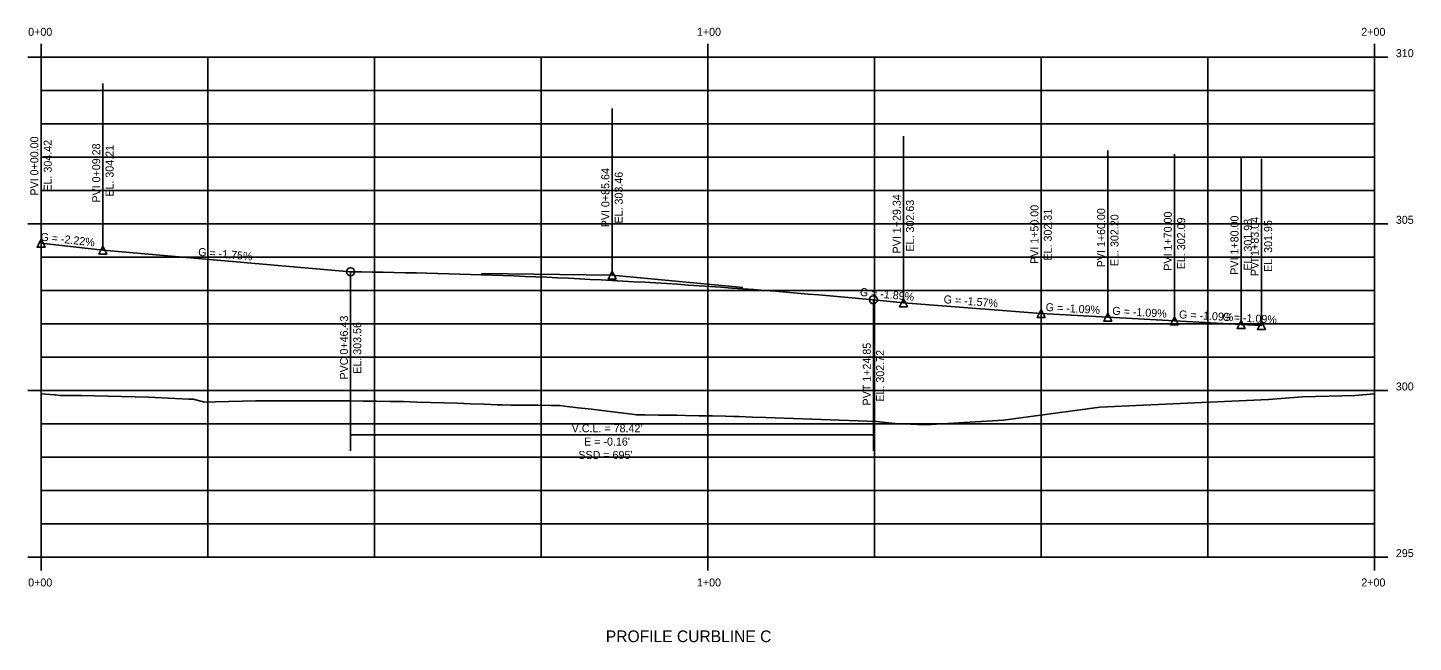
# Model space of a CAD drawing. Extents: x 916627 to 921213, y 329780 to 330157.
# Drawn here: x 920569.3 to 920777.1, y 329813.5 to 329905.7 of the extents above; entities that cross this region are included whole.
import ezdxf

# ---------------------------------------------------------------- set-up
doc = ezdxf.new("R2010")
doc.units = 0
for name, color, linetype in [('D_Roadway_Centerline', 7, 'Continuous'), ('D_Roadway_Centerline_Bearings', 7, 'Continuous'), ('D_Roadway_Centerline_CurveData', 7, 'Continuous'), ('D_Roadway_Centerline_Text', 7, 'Continuous')]:
    doc.layers.add(name, color=color, linetype=linetype)

msp = doc.modelspace()

# ---------------------------------------------------------------- linework, layer by layer
at = {"layer": 'D_Roadway_Centerline'}
for p, q in [((920571.31, 329903.28), (920571.31, 329901.28)), ((920671.31, 329903.28), (920671.31, 329901.28)), ((920771.31, 329903.28), (920771.31, 329901.28)), ((920771.31, 329903.28), (920771.31, 329901.28)), ((920569.31, 329901.28), (920571.31, 329901.28)), ((920569.31, 329901.28), (920571.31, 329901.28)), ((920571.31, 329901.28), (920771.31, 329901.28)), ((920571.31, 329826.28), (920571.31, 329901.28)), ((920671.31, 329826.28), (920671.31, 329901.28)), ((920771.31, 329826.28), (920771.31, 329901.28)), ((920773.31, 329901.28), (920771.31, 329901.28)), ((920773.31, 329901.28), (920771.31, 329901.28)), ((920569.31, 329876.28), (920571.31, 329876.28)), ((920571.31, 329876.28), (920771.31, 329876.28)), ((920773.31, 329876.28), (920771.31, 329876.28)), ((920571.31, 329873.36), (920580.59, 329872.33)), ((920580.59, 329872.33), (920617.74, 329869.08)), ((920696.16, 329864.88), (920700.65, 329864.45)), ((920700.65, 329864.45), (920721.31, 329862.83)), ((920721.31, 329862.83), (920731.31, 329862.29)), ((920731.31, 329862.29), (920741.31, 329861.74)), ((920741.31, 329861.74), (920751.31, 329861.19)), ((920751.31, 329861.19), (920754.35, 329861.03)), ((920569.31, 329851.28), (920571.31, 329851.28)), ((920571.31, 329851.28), (920771.31, 329851.28)), ((920773.31, 329851.28), (920771.31, 329851.28)), ((920569.31, 329826.28), (920571.31, 329826.28)), ((920571.31, 329824.28), (920571.31, 329826.28)), ((920571.31, 329826.28), (920771.31, 329826.28)), ((920671.31, 329824.28), (920671.31, 329826.28)), ((920773.31, 329826.28), (920771.31, 329826.28)), ((920771.31, 329824.28), (920771.31, 329826.28)), ((920771.31, 329824.28), (920771.31, 329826.28))]:
    msp.add_line(p, q, dxfattribs=at)
msp.add_lwpolyline([(920617.74, 329869.08), (920619.38, 329869.06), (920621.01, 329869.03), (920622.64, 329869.01), (920624.28, 329868.98), (920625.91, 329868.94), (920627.55, 329868.91), (920629.18, 329868.87), (920630.81, 329868.83), (920632.45, 329868.78), (920634.08, 329868.74), (920635.71, 329868.69), (920637.35, 329868.63), (920638.98, 329868.58), (920640.62, 329868.52), (920642.25, 329868.46), (920643.88, 329868.4), (920645.52, 329868.33), (920647.15, 329868.26), (920648.78, 329868.19), (920650.42, 329868.11), (920652.05, 329868.03), (920653.69, 329867.95), (920655.32, 329867.87), (920658.59, 329867.7), (920660.22, 329867.6), (920661.85, 329867.51), (920663.49, 329867.41), (920665.12, 329867.31), (920666.76, 329867.21), (920668.39, 329867.1), (920670.02, 329866.99), (920671.66, 329866.88), (920673.29, 329866.77), (920674.92, 329866.65), (920676.56, 329866.53), (920678.19, 329866.41), (920679.83, 329866.28), (920681.46, 329866.16), (920683.09, 329866.02), (920684.73, 329865.89), (920686.36, 329865.75), (920687.99, 329865.62), (920689.63, 329865.47), (920691.26, 329865.33), (920692.9, 329865.18), (920694.53, 329865.03), (920696.16, 329864.88)], dxfattribs=at)
at = {"layer": 'D_Roadway_Centerline_Bearings'}
msp.add_lwpolyline([(920571.31, 329850.78), (920573.33, 329850.63), (920573.5, 329850.62), (920574.13, 329850.54), (920575.34, 329850.54), (920577.35, 329850.52), (920579.37, 329850.49), (920581.38, 329850.45), (920583.39, 329850.4), (920585.41, 329850.34), (920587.42, 329850.27), (920589.43, 329850.19), (920591.45, 329850.1), (920593.46, 329850), (920594.13, 329849.96), (920595.47, 329849.62), (920595.74, 329849.55), (920597.49, 329849.59), (920599.5, 329849.63), (920601.51, 329849.67), (920603.53, 329849.71), (920604.68, 329849.74), (920605.54, 329849.74), (920607.55, 329849.74), (920609.57, 329849.75), (920611.58, 329849.74), (920613.59, 329849.73), (920615.61, 329849.72), (920617.62, 329849.71), (920619.63, 329849.69), (920619.97, 329849.68), (920621.65, 329849.67), (920623.66, 329849.65), (920624.92, 329849.63), (920625.67, 329849.61), (920627.69, 329849.55), (920629.7, 329849.49), (920631.71, 329849.43), (920633.73, 329849.36), (920635.74, 329849.29), (920637.75, 329849.22), (920639.77, 329849.14), (920640.47, 329849.11), (920641.78, 329849.1), (920643.79, 329849.08), (920645.81, 329849.06), (920647.82, 329849.03), (920649.18, 329849.01), (920649.83, 329848.94), (920651.85, 329848.7), (920653.86, 329848.46), (920655.87, 329848.21), (920657.89, 329847.96), (920659.9, 329847.71), (920660.56, 329847.62), (920661.91, 329847.61), (920663.93, 329847.58), (920665.94, 329847.57), (920666.67, 329847.56), (920667.95, 329847.53), (920669.97, 329847.49), (920671.98, 329847.46), (920673.99, 329847.42), (920675.21, 329847.4), (920676.01, 329847.37), (920678.02, 329847.3), (920680.03, 329847.22), (920696.64, 329846.63), (920699.36, 329846.31), (920703.95, 329846.13), (920715.66, 329846.81), (920730.1, 329848.79), (920736.66, 329849.08), (920755.42, 329849.94), (920760.49, 329850.32), (920768.34, 329850.55), (920771.31, 329850.78)], dxfattribs=at)
at = {"layer": 'D_Roadway_Centerline_CurveData'}
for p, q in [((920571.31, 329873.36), (920571.31, 329898.36)), ((920580.59, 329872.33), (920580.59, 329897.33)), ((920656.95, 329868.59), (920656.95, 329893.59)), ((920700.65, 329864.45), (920700.65, 329889.45)), ((920721.31, 329862.83), (920721.31, 329887.83)), ((920731.31, 329862.29), (920731.31, 329887.29)), ((920741.31, 329861.74), (920741.31, 329886.74)), ((920751.31, 329861.19), (920751.31, 329886.19)), ((920754.35, 329861.03), (920754.35, 329886.03)), ((920617.74, 329869.08), (920617.74, 329844.08)), ((920637.35, 329868.84), (920656.95, 329868.59)), ((920656.95, 329868.59), (920676.56, 329866.73)), ((920696.16, 329864.88), (920696.16, 329842.21)), ((920617.74, 329844.08), (920617.74, 329842.21))]:
    msp.add_line(p, q, dxfattribs=at)
for points in [[(920571.31, 329873.96), (920571.91, 329872.76), (920570.71, 329872.76)], [(920580.59, 329872.93), (920581.19, 329871.73), (920579.99, 329871.73)], [(920656.95, 329869.19), (920657.55, 329867.99), (920656.35, 329867.99)], [(920700.65, 329865.05), (920701.25, 329863.85), (920700.05, 329863.85)], [(920721.31, 329863.43), (920721.91, 329862.23), (920720.71, 329862.23)], [(920731.31, 329862.89), (920731.91, 329861.69), (920730.71, 329861.69)], [(920741.31, 329862.34), (920741.91, 329861.14), (920740.71, 329861.14)], [(920751.31, 329861.79), (920751.91, 329860.59), (920750.71, 329860.59)], [(920754.35, 329861.63), (920754.95, 329860.43), (920753.75, 329860.43)]]:
    msp.add_lwpolyline(points, close=True, dxfattribs=at)
msp.add_lwpolyline([(920617.74, 329844.61), (920696.16, 329844.61)], dxfattribs=at)
for centre in [(920617.74, 329869.08), (920696.16, 329864.88)]:
    msp.add_circle(centre, 0.6, dxfattribs=at)
at = {"layer": 'D_Roadway_Centerline_Text'}
for p, q in [((920596.31, 329826.28), (920596.31, 329901.28)), ((920621.31, 329826.28), (920621.31, 329901.28)), ((920646.31, 329826.28), (920646.31, 329901.28)), ((920696.31, 329826.28), (920696.31, 329901.28)), ((920721.31, 329826.28), (920721.31, 329901.28)), ((920746.31, 329826.28), (920746.31, 329901.28)), ((920571.31, 329896.28), (920771.31, 329896.28)), ((920571.31, 329891.28), (920771.31, 329891.28)), ((920571.31, 329886.28), (920771.31, 329886.28)), ((920571.31, 329881.28), (920771.31, 329881.28)), ((920571.31, 329871.28), (920771.31, 329871.28)), ((920571.31, 329866.28), (920771.31, 329866.28)), ((920571.31, 329861.28), (920771.31, 329861.28)), ((920571.31, 329856.28), (920771.31, 329856.28)), ((920571.31, 329846.28), (920771.31, 329846.28)), ((920571.31, 329841.28), (920771.31, 329841.28)), ((920571.31, 329836.28), (920771.31, 329836.28)), ((920571.31, 329831.28), (920771.31, 329831.28))]:
    msp.add_line(p, q, dxfattribs=at)

# ---------------------------------------------------------------- texts
at = {"layer": 'D_Roadway_Centerline_CurveData'}
for s, height, p in [('0+00', 1.2, (920569.38, 329904.48)), ('1+00', 1.2, (920669.68, 329904.48)), ('2+00', 1.2, (920769.33, 329904.48)), ('310', 1.2, (920774.51, 329901.28)), ('310', 1.2, (920774.51, 329901.28)), ('305', 1.2, (920774.51, 329876.28)), ('300', 1.2, (920774.51, 329851.28)), ("V.C.L. = 78.42'", 1.2, (920650.9, 329845.01)), ("E = -0.16'", 1.2, (920652.76, 329843.01)), ("SSD = 695'", 1.2, (920651.9, 329841.01)), ('295', 1.2, (920774.51, 329826.28)), ('0+00', 1.2, (920569.38, 329821.88)), ('1+00', 1.2, (920669.68, 329821.88)), ('2+00', 1.2, (920769.33, 329821.88)), ('PROFILE CURBLINE C', 1.75, (920656.02, 329813.53))]:
    msp.add_text(s, height=height, dxfattribs=at).set_placement(p)
for s, rotation, p in [('PVI 0+00.00', 90, (920570.91, 329880.51)), ('EL. 304.42', 90, (920572.91, 329881.11)), ('PVI 0+09.28', 90, (920580.19, 329879.46)), ('EL. 304.21', 90, (920582.19, 329880.35)), ('PVI 0+85.64', 90, (920656.55, 329875.76)), ('EL. 303.46', 90, (920658.55, 329876.32)), ('PVI 1+29.34', 90, (920700.25, 329871.84)), ('EL. 302.63', 90, (920702.25, 329872.12)), ('PVI 1+50.00', 90, (920720.91, 329870.25)), ('EL. 302.31', 90, (920722.91, 329870.77)), ('PVI 1+60.00', 90, (920730.91, 329869.75)), ('EL. 302.20', 90, (920732.91, 329869.94)), ('PVI 1+70.00', 90, (920740.91, 329869.24)), ('PVI 1+80.00', 90, (920750.91, 329868.64)), ('EL. 302.09', 90, (920742.91, 329869.46)), ('EL. 301.98', 90, (920752.91, 329869.26)), ('PVI 1+83.04', 90, (920753.95, 329868.44)), ('EL. 301.95', 90, (920755.95, 329869.07)), ('G = -2.22%', 353.6573, (920571.19, 329873.78)), ('G = -1.75%', 355.0008, (920594.84, 329871.49)), ('G = -1.89%', 354.5883, (920694.08, 329865.48)), ('G = -1.57%', 355.5191, (920706.65, 329864.38)), ('G = -1.09%', 356.8721, (920721.96, 329863.2)), ('G = -1.09%', 356.8717, (920731.96, 329862.65)), ('G = -1.09%', 356.8801, (920741.96, 329862.11)), ('G = -1.09%', 356.89, (920748.48, 329861.75)), ('PVC 0+46.43', 90, (920617.34, 329852.92)), ('EL. 303.56', 90, (920619.34, 329853.78)), ('PVT 1+24.85', 90, (920695.76, 329849.03)), ('EL. 302.72', 90, (920697.76, 329849.6))]:
    msp.add_text(s, height=1.2, rotation=rotation, dxfattribs=at).set_placement(p)

doc.saveas('drawing.dxf')
